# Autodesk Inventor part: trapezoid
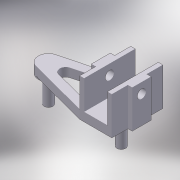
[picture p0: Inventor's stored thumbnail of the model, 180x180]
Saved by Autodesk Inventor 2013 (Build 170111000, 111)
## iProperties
Shininess: 50.0
Length Units: 11269
Angle Units: 11279
Time Units: 11290
Mass Units: 11283
Length Display Precision: 3
Angle Display Precision: 2
Created: 2002-03
Part Number: trapezoid
Material: Aluminum-6061
Document SubType Name: Modeling
Designer: =<Author>
Density: 2.71 g/cm^3
Description: =<Part Number>
Density: 2.71
Volumn: 15.647870940102377
Area: 87.18559119499753
PropertySet Name: Model Information
Control State: 0
Master: False
Checked Out: True
Last Check In Date: 2008-10-15
Checked Out Date: 2008-10-15
Author: LAlexey
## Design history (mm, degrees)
sketch "Sketch1"
  geometry: L1 (-27.161, 9.036)-(13.62, 19.766); L2 (13.62, 19.766)-(35.62, 19.766); L3 (35.62, 19.766)-(35.62, 8.766); L4 (35.62, 8.766)-(38.62, 8.766); L5 (38.62, 8.766)-(38.62, -4.234); L6 (38.62, -4.234)-(35.62, -4.234); L7 (35.62, -4.234)-(35.62, -15.234); L8 (35.62, -15.234)-(13.62, -15.234); L9 (13.62, -15.234)-(-27.161, -4.503); L10 (-29.31, 2.266)-(10.62, 12.773); L11 (10.62, 12.773)-(10.62, -8.24); L12 (10.62, -8.24)-(-29.31, 2.266); A1 r 7 centre (-25.38, 2.266) between (-27.161, 9.036) and (-27.161, -4.503)
  constraints: 24 end point, 7 perpendicular, 4 equal length, 2 parallel, 2 point on circle, 2 tangent, 1 centre point, 1 horizontal
  dimensions: "d0" = 35 distance between parallel lines of L8 L2; "d1" = 7 radius of A1; "d2" = 13 distance of L4.end L5.end; "d3" = 22 distance of L7.end L8.end; "d4" = 3 distance between parallel lines of L7 L5; "d5" = 3 distance from line of L8.end L11; "d6" = 6 distance between parallel lines of L1 L10; "d8" = 6 distance between parallel lines of L9 L12; "d9" = 61 distance from line of L7 A1.centre
extrude "Extrusion1" new body sketch "Sketch1" distance "d10" = 6; taper "d11" = 0 deg
fillet "Fillet1" dims "d12" = 4
sketch "Sketch2"
  geometry: L1 (-35.62, 19.766)-(-35.62, 8.766) reference; C1 r 7 at (25.38, 2.266); C2 r 7 at (-24.62, 2.266); A1 r 7 centre (25.38, 2.266) between (27.161, -4.503) and (27.161, 9.036) reference
  constraints: 2 centre point, 2 equal radius, 1 coincident
  dimensions: "d13" = 11 distance from line of L1 C2.centre; "d14" = 50 distance of A1.centre C2.centre
extrude "Extrusion2" join sketch "Sketch2" distance "d15" = 1; taper "d16" = 0 deg
sketch "Sketch3"
  geometry: L1 (10.62, 7.584)-(10.62, -3.052) reference; L2 (13.62, 19.766)-(35.62, 19.766) reference; L3 (35.62, -15.234)-(13.62, -15.234) reference; L4 (35.62, -4.234)-(35.62, -15.234) reference; L5 (38.62, -4.234)-(35.62, -4.234) reference; L6 (38.62, 8.766)-(38.62, -4.234) reference; L7 (35.62, 8.766)-(38.62, 8.766) reference; L8 (35.62, 19.766)-(35.62, 8.766) reference; L9 (13.62, -15.234)-(13.62, -4.234); L10 (13.62, -4.234)-(10.62, -4.234); L11 (10.62, 8.766)-(13.62, 8.766); L12 (13.62, 8.766)-(13.62, 19.766); L13 (10.62, 8.766)-(10.62, -4.234); L14 (16.62, 19.766)-(16.62, -15.234); L15 (32.62, -15.234)-(32.62, 19.766)
  constraints: 14 end point, 6 point on line, 4 perpendicular, 3 parallel, 2 equal length
  dimensions: "d17" = 16 distance between parallel lines of L15 L14; "d18" = 3 distance between parallel lines of L14 L12
extrude "Extrusion3" join sketch "Sketch3" distance "d19" = 20; taper "d20" = 0 deg
sketch "Sketch4"
  geometry: L1 (6, -1.182)-(6, 0) reference; L2 (6, -1.182)-(26, -1.182) reference; C1 r 3 at (19, 5.318)
  constraints: 1 centre point
  dimensions: "d21" = 6 diameter of C1; "d22" = 13 distance from line of L1 C1.centre; "d23" = 6.5 distance from line of L2 C1.centre
extrude "Extrusion4" cut sketch "Sketch4" distance "d24" = 50; taper "d25" = 0 deg
sketch "Sketch5"
  geometry: C1 r 7 at (0, 0) reference; C2 r 7 at (-50, 0) reference; C3 r 3 at (0, 0); C4 r 3 at (-50, 0)
  constraints: 2 centre point, 2 coincident, 1 equal radius
  dimensions: "d26" = 6 diameter of C3
extrude "Extrusion5" join sketch "Sketch5" distance "d27" = 18; taper "d28" = 0 deg
workaxis "Work Axis1"
workaxis "Work Axis2"
workplane "Work Plane1"
workaxis "Work Axis3"
body "Solid1"
